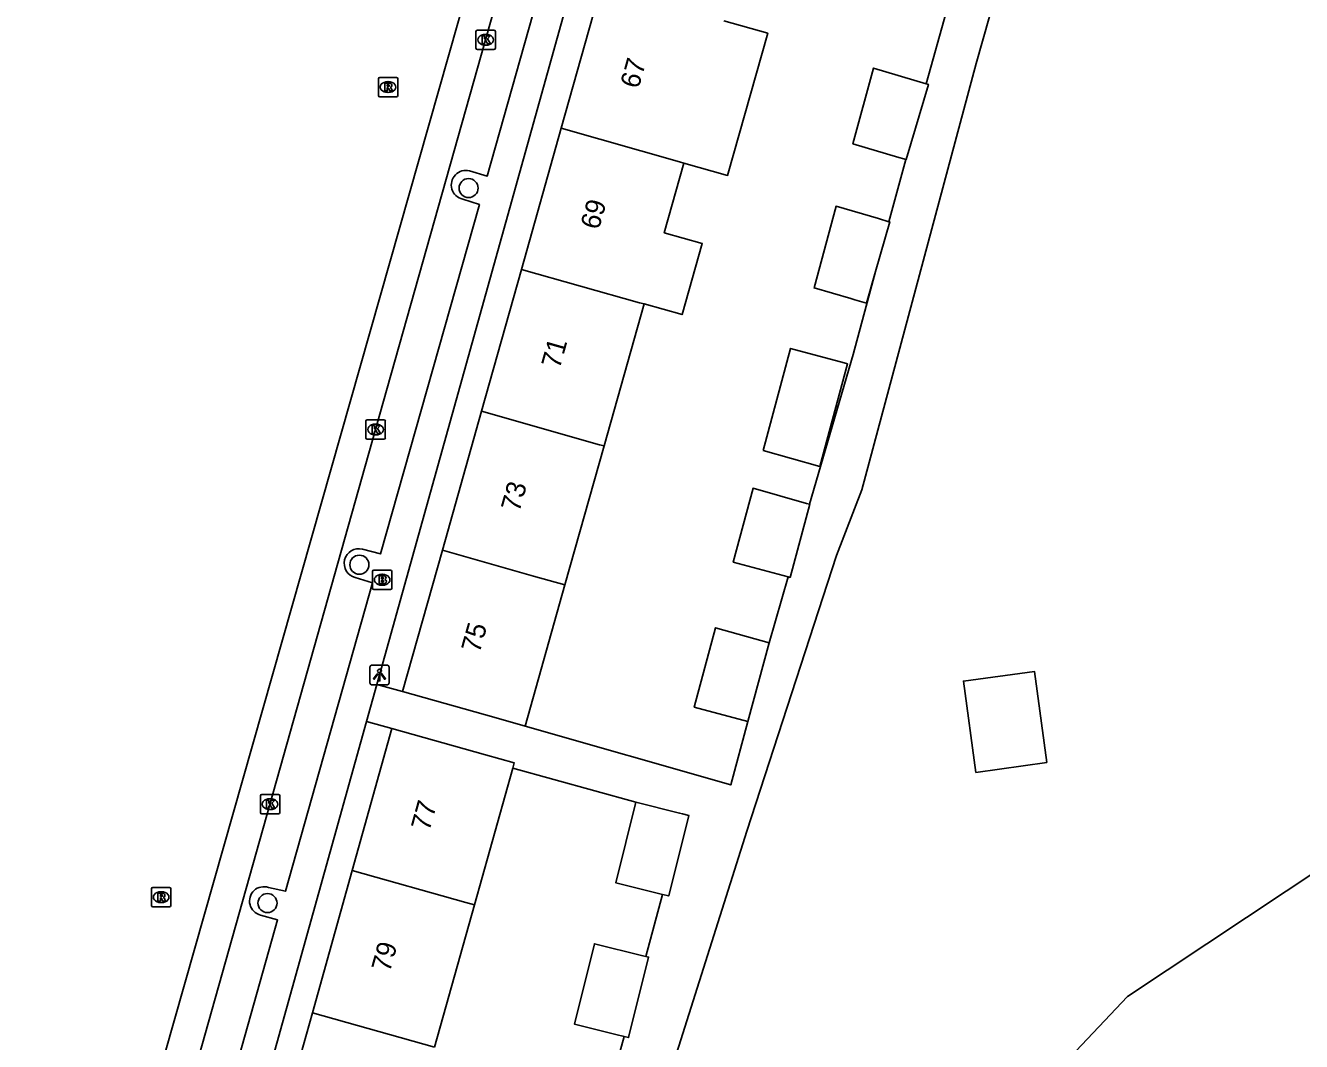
# Model space of a CAD drawing. Extents: x 163150 to 163546, y 380933 to 381635.
# Drawn here: x 163161.3 to 163226.9, y 381288.4 to 381340.6 of the extents above; entities that cross this region are included whole.
import ezdxf

# ---------------------------------------------------------------- set-up
doc = ezdxf.new("R2010")
doc.units = 0
for name, color, linetype in [('IMGEO_Boom', 7, 'Continuous'), ('IMGEO_Brandkraan', 7, 'Continuous'), ('IMGEO_Fietspad_gesloten', 7, 'Continuous'), ('IMGEO_Kolk', 7, 'Continuous'), ('IMGEO_Lichtpunt', 7, 'Continuous'), ('IMGEO_Pand', 7, 'Continuous'), ('IMGEO_Pand_nummerreeks', 7, 'Continuous'), ('IMGEO_Rijbaan_lokaal_gesloten', 7, 'Continuous'), ('IMGEO_Rioolput', 7, 'Continuous'), ('IMGEO_Voetpad_open', 7, 'Continuous')]:
    doc.layers.add(name, color=color, linetype=linetype)

msp = doc.modelspace()

# ---------------------------------------------------------------- linework, layer by layer
at = {"layer": 'IMGEO_Boom'}
for centre in [(163184.057, 381332.261), (163178.441, 381312.89), (163173.717, 381295.486)]:
    msp.add_circle(centre, 0.489, dxfattribs=at)
at = {"layer": 'IMGEO_Brandkraan'}
for p, q in [((163179.113, 381311.689), (163179.113, 381312.541)), ((163179.188, 381312.615), (163180.04, 381312.615)), ((163179.601, 381312.395), (163179.626, 381312.395)), ((163180.114, 381312.541), (163180.114, 381311.689)), ((163180.04, 381311.615), (163179.188, 381311.615)), ((163179.624, 381311.835), (163179.599, 381311.835))]:
    msp.add_line(p, q, dxfattribs=at)
for points in [[(163179.113, 381311.689), (163179.113, 381312.541)], [(163179.188, 381312.615), (163180.04, 381312.615)], [(163179.461, 381312.315), (163179.461, 381311.915), (163179.674, 381311.915)], [(163179.692, 381312.315), (163179.461, 381312.315)], [(163179.64, 381312.234), (163179.586, 381312.234), (163179.586, 381312.158)], [(163179.586, 381312.158), (163179.639, 381312.158)], [(163179.648, 381312.082), (163179.586, 381312.082), (163179.586, 381312.001)], [(163180.114, 381312.541), (163180.114, 381311.689)], [(163180.04, 381311.615), (163179.188, 381311.615)], [(163179.586, 381312.001), (163179.648, 381312.001)]]:
    msp.add_lwpolyline(points, dxfattribs=at)
for centre, radius, start, end in [((163179.19, 381312.539), 0.0765, 91.55205, 178.44795), ((163179.19, 381312.539), 0.0765, 91.55205, 178.44795), ((163179.641, 381312.196), 0.0379, 267.82845, 90.93552), ((163179.649, 381312.041), 0.0404, 269.87594, 90.50774), ((163179.696, 381312.17), 0.145, 59.4692, 91.53667), ((163179.721, 381312.217), 0.0922, 285.51372, 58.15012), ((163179.726, 381312.025), 0.105, 301.31148, 78.98903), ((163180.038, 381312.539), 0.0765, 1.55205, 88.44795), ((163180.038, 381312.539), 0.0765, 1.55205, 88.44795), ((163179.19, 381311.691), 0.0765, 181.55205, 268.44795), ((163179.19, 381311.691), 0.0765, 181.55205, 268.44795), ((163179.68, 381312.166), 0.251, 268.66757, 293.53466), ((163180.038, 381311.691), 0.0765, 271.55205, 358.44795), ((163180.038, 381311.691), 0.0765, 271.55205, 358.44795)]:
    msp.add_arc(centre, radius, start, end, dxfattribs=at)
for centre, major_axis, ratio, start_param, end_param in [((163179.6, 381312.115), (-0.387, 0.002), 0.722429, 4.712389, 7.853982), ((163179.625, 381312.115), (-0.39, 0.002), 0.717154, 1.570796, 4.712389)]:
    msp.add_ellipse(centre, major_axis=major_axis, ratio=ratio, start_param=start_param, end_param=end_param, dxfattribs=at)
at = {"layer": 'IMGEO_Fietspad_gesloten'}
msp.add_lwpolyline([(163161.275, 381254.943), (163161.793, 381257.499), (163168.406, 381281.262), (163179.271, 381319.843), (163184.929, 381339.887), (163190.292, 381358.866), (163196.902, 381382.418), (163200.87, 381396.808), (163201.039, 381397.48), (163201.153, 381398.031), (163202.014, 381403.062), (163202.729, 381407.262)], dxfattribs=at)
at = {"layer": 'IMGEO_Kolk'}
for p, q in [((163184.433, 381339.461), (163184.433, 381340.313)), ((163184.508, 381340.387), (163185.36, 381340.387)), ((163185.434, 381340.313), (163185.434, 381339.461)), ((163184.944, 381339.607), (163184.919, 381339.607)), ((163184.921, 381340.167), (163184.946, 381340.167)), ((163185.36, 381339.387), (163184.508, 381339.387)), ((163178.775, 381319.417), (163178.775, 381320.269)), ((163178.85, 381320.343), (163179.702, 381320.343)), ((163179.263, 381320.123), (163179.288, 381320.123)), ((163179.776, 381320.269), (163179.776, 381319.417)), ((163179.702, 381319.343), (163178.85, 381319.343)), ((163179.286, 381319.563), (163179.261, 381319.563)), ((163173.349, 381300.149), (163173.349, 381301.001)), ((163173.424, 381301.075), (163174.276, 381301.075)), ((163174.35, 381301.001), (163174.35, 381300.149)), ((163173.86, 381300.295), (163173.835, 381300.295)), ((163173.837, 381300.855), (163173.862, 381300.855)), ((163174.276, 381300.075), (163173.424, 381300.075))]:
    msp.add_line(p, q, dxfattribs=at)
for points in [[(163184.433, 381339.461), (163184.433, 381340.313)], [(163184.508, 381340.387), (163185.36, 381340.387)], [(163185.434, 381340.313), (163185.434, 381339.461)], [(163184.754, 381340.087), (163184.877, 381340.087), (163184.877, 381339.936), (163185.007, 381340.087), (163185.171, 381340.087), (163185.025, 381339.936), (163185.178, 381339.687), (163185.026, 381339.687), (163184.941, 381339.851), (163184.877, 381339.784), (163184.877, 381339.687), (163184.754, 381339.687), (163184.754, 381340.087)], [(163185.36, 381339.387), (163184.508, 381339.387)], [(163178.775, 381319.417), (163178.775, 381320.269)], [(163178.85, 381320.343), (163179.702, 381320.343)], [(163179.096, 381320.043), (163179.219, 381320.043), (163179.219, 381319.892), (163179.349, 381320.043), (163179.513, 381320.043), (163179.367, 381319.892), (163179.52, 381319.643), (163179.368, 381319.643), (163179.283, 381319.807), (163179.219, 381319.74), (163179.219, 381319.643), (163179.096, 381319.643), (163179.096, 381320.043)], [(163179.776, 381320.269), (163179.776, 381319.417)], [(163179.702, 381319.343), (163178.85, 381319.343)], [(163173.349, 381300.149), (163173.349, 381301.001)], [(163173.424, 381301.075), (163174.276, 381301.075)], [(163174.35, 381301.001), (163174.35, 381300.149)], [(163173.67, 381300.775), (163173.793, 381300.775), (163173.793, 381300.624), (163173.923, 381300.775), (163174.087, 381300.775), (163173.941, 381300.624), (163174.094, 381300.375), (163173.942, 381300.375), (163173.857, 381300.539), (163173.793, 381300.472), (163173.793, 381300.375), (163173.67, 381300.375), (163173.67, 381300.775)], [(163174.276, 381300.075), (163173.424, 381300.075)]]:
    msp.add_lwpolyline(points, dxfattribs=at)
for centre, start, end in [((163184.51, 381340.311), 91.55205, 178.44795), ((163184.51, 381340.311), 91.55205, 178.44795), ((163185.358, 381340.311), 1.55205, 88.44795), ((163185.358, 381340.311), 1.55205, 88.44795), ((163184.51, 381339.463), 181.55205, 268.44795), ((163184.51, 381339.463), 181.55205, 268.44795), ((163185.358, 381339.463), 271.55205, 358.44795), ((163185.358, 381339.463), 271.55205, 358.44795), ((163178.852, 381320.267), 91.55205, 178.44795), ((163178.852, 381320.267), 91.55205, 178.44795), ((163179.7, 381320.267), 1.55205, 88.44795), ((163179.7, 381320.267), 1.55205, 88.44795), ((163178.852, 381319.419), 181.55205, 268.44795), ((163178.852, 381319.419), 181.55205, 268.44795), ((163179.7, 381319.419), 271.55205, 358.44795), ((163179.7, 381319.419), 271.55205, 358.44795), ((163173.426, 381300.999), 91.55205, 178.44795), ((163173.426, 381300.999), 91.55205, 178.44795), ((163174.274, 381300.999), 1.55205, 88.44795), ((163174.274, 381300.999), 1.55205, 88.44795), ((163173.426, 381300.151), 181.55205, 268.44795), ((163173.426, 381300.151), 181.55205, 268.44795), ((163174.274, 381300.151), 271.55205, 358.44795), ((163174.274, 381300.151), 271.55205, 358.44795)]:
    msp.add_arc(centre, 0.0765, start, end, dxfattribs=at)
for centre, major_axis, ratio, start_param, end_param in [((163184.92, 381339.887), (-0.387, 0.002), 0.722429, 4.712389, 7.853982), ((163184.945, 381339.887), (-0.39, 0.002), 0.717154, 1.570796, 4.712389), ((163179.262, 381319.843), (-0.387, 0.002), 0.722429, 4.712389, 7.853982), ((163179.287, 381319.843), (-0.39, 0.002), 0.717154, 1.570796, 4.712389), ((163173.836, 381300.575), (-0.387, 0.002), 0.722429, 4.712389, 7.853982), ((163173.861, 381300.575), (-0.39, 0.002), 0.717154, 1.570796, 4.712389)]:
    msp.add_ellipse(centre, major_axis=major_axis, ratio=ratio, start_param=start_param, end_param=end_param, dxfattribs=at)
at = {"layer": 'IMGEO_Lichtpunt'}
for p, q in [((163178.978, 381307.62), (163178.978, 381306.813)), ((163178.978, 381307.62), (163178.978, 381306.813)), ((163179.88, 381307.715), (163179.072, 381307.715)), ((163179.88, 381307.715), (163179.072, 381307.715)), ((163179.974, 381306.813), (163179.974, 381307.62)), ((163179.974, 381306.813), (163179.974, 381307.62)), ((163179.072, 381306.719), (163179.88, 381306.719)), ((163179.072, 381306.719), (163179.88, 381306.719))]:
    msp.add_line(p, q, dxfattribs=at)
for points in [[(163179.352, 381307.284), (163179.391, 381307.256), (163179.203, 381306.994), (163179.165, 381307.021), (163179.352, 381307.284)], [(163179.454, 381307.236), (163179.501, 381307.236), (163179.501, 381306.914), (163179.454, 381306.914), (163179.454, 381307.236)], [(163179.564, 381307.256), (163179.602, 381307.283), (163179.789, 381307.021), (163179.75, 381306.993), (163179.564, 381307.256)]]:
    msp.add_lwpolyline(points, dxfattribs=at)
msp.add_circle((163179.477, 381307.418), 0.0994, dxfattribs=at)
for centre, start, end in [((163179.072, 381307.62), 90, 180), ((163179.072, 381307.62), 90, 180), ((163179.88, 381307.62), 0, 90), ((163179.88, 381307.62), 0, 90), ((163179.072, 381306.813), 180, 270), ((163179.072, 381306.813), 180, 270), ((163179.88, 381306.813), 270, 0), ((163179.88, 381306.813), 270, 360)]:
    msp.add_arc(centre, 0.0946, start, end, dxfattribs=at)
at = {"layer": 'IMGEO_Pand'}
for points in [[(163190.882, 381342.639), (163188.825, 381335.337)], [(163195.127, 381333.55), (163197.374, 381332.915), (163199.439, 381340.22), (163197.185, 381340.857)], [(163206.533, 381333.732), (163206.432, 381333.762), (163206.181, 381333.837), (163203.817, 381334.538), (163204.869, 381338.436), (163207.581, 381337.631)], [(163207.581, 381337.631), (163207.703, 381337.595), (163206.554, 381333.726), (163206.533, 381333.732)], [(163188.825, 381335.337), (163186.781, 381328.079)], [(163195.127, 381333.55), (163194.895, 381333.616), (163188.825, 381335.337)], [(163193.085, 381326.302), (163195.035, 381325.75), (163196.07, 381329.405), (163194.115, 381329.959), (163195.127, 381333.55)], [(163204.982, 381327.966), (163204.513, 381326.347), (163203.921, 381326.519), (163203.711, 381326.58), (163201.818, 381327.129), (163202.95, 381331.323), (163205.13, 381330.691), (163205.673, 381330.533)], [(163205.673, 381330.533), (163205.722, 381330.519), (163204.982, 381327.966)], [(163186.781, 381328.079), (163184.724, 381320.778)], [(163186.781, 381328.079), (163192.842, 381326.362), (163193.085, 381326.302)], [(163191.028, 381318.999), (163193.085, 381326.302)], [(163199.206, 381318.759), (163202.119, 381317.934), (163203.541, 381323.228), (163203.376, 381323.272), (163200.617, 381324.012), (163199.206, 381318.759)], [(163184.724, 381320.778), (163182.71, 381313.629)], [(163191.028, 381318.999), (163190.78, 381319.062), (163184.724, 381320.778)], [(163189.013, 381311.846), (163191.028, 381318.999)], [(163200.497, 381312.262), (163197.665, 381313.023), (163198.686, 381316.821), (163201.434, 381316.043), (163201.588, 381316)], [(163201.588, 381316), (163201.598, 381315.997), (163200.588, 381312.237), (163200.497, 381312.262)], [(163182.71, 381313.629), (163180.663, 381306.36)], [(163189.013, 381311.846), (163187.391, 381312.302), (163182.71, 381313.629)], [(163186.97, 381304.591), (163189.013, 381311.846)], [(163187.968, 381233.07), (163193.271, 381250), (163197.467, 381263.396), (163206.151, 381278.206), (163217.937, 381290.687), (163232.209, 381300.168), (163248.202, 381306.183), (163251.969, 381306.664), (163251.737, 381308.49), (163248.676, 381308.083), (163248.28, 381310.782), (163251.461, 381311.208), (163254.337, 381311.635), (163256.45, 381311.907)], [(163198.421, 381304.829), (163195.663, 381305.57), (163196.758, 381309.646), (163199.506, 381308.868)], [(163199.506, 381308.868), (163198.421, 381304.829)], [(163213.795, 381302.708), (163210.142, 381302.21), (163209.502, 381306.907), (163213.155, 381307.404), (163213.795, 381302.708)], [(163180.663, 381306.36), (163185.478, 381305.01), (163186.97, 381304.591)], [(163178.075, 381297.165), (163180.119, 381304.459)], [(163186.332, 381302.428), (163186.406, 381302.694), (163184.933, 381303.108), (163180.119, 381304.459)], [(163186.332, 381302.428), (163184.36, 381295.392)], [(163194.036, 381295.935), (163191.624, 381296.533), (163192.652, 381300.67)], [(163194.036, 381295.935), (163194.353, 381295.856), (163195.379, 381299.992), (163195.063, 381300.071), (163194.903, 381300.111), (163192.652, 381300.67)], [(163178.075, 381297.165), (163176.023, 381289.839)], [(163184.36, 381295.392), (163183.923, 381295.514), (163178.075, 381297.165)], [(163184.36, 381295.392), (163182.308, 381288.068)], [(163192.051, 381288.626), (163191.992, 381288.641), (163191.694, 381288.715), (163189.498, 381289.26), (163190.526, 381293.396), (163193.019, 381292.777), (163193.168, 381292.74)], [(163193.168, 381292.74), (163193.31, 381292.705), (163192.282, 381288.569), (163192.051, 381288.626)], [(163176.023, 381289.839), (163174.025, 381282.711)], [(163182.308, 381288.068), (163176.023, 381289.839)]]:
    msp.add_lwpolyline(points, dxfattribs=at)
at = {"layer": 'IMGEO_Rijbaan_lokaal_gesloten'}
msp.add_lwpolyline([(163166.425, 381280.691), (163188.546, 381358.485), (163194.244, 381378.759), (163197.853, 381391.449), (163199.503, 381397.64), (163199.813, 381399.806), (163200.997, 381406.978), (163202.361, 381414.066), (163203.421, 381419.565), (163203.421, 381421.474), (163203.421, 381430.45), (163203.421, 381436.022), (163203.704, 381437.827), (163206.489, 381449.486), (163214.12, 381481.676), (163216.801, 381492.716), (163218.451, 381497.565), (163223.711, 381513.764), (163241.568, 381568.239), (163248.986, 381592.289), (163253.519, 381605.619), (163255.545, 381608.986), (163259.826, 381616.311)], dxfattribs=at)
at = {"layer": 'IMGEO_Rioolput'}
for p, q in [((163179.417, 381337.03), (163179.417, 381337.882)), ((163179.492, 381337.956), (163180.344, 381337.956)), ((163179.905, 381337.736), (163179.93, 381337.736)), ((163180.418, 381337.882), (163180.418, 381337.03)), ((163179.928, 381337.176), (163179.903, 381337.176)), ((163180.344, 381336.956), (163179.492, 381336.956)), ((163167.825, 381296.292), (163168.677, 381296.292)), ((163167.75, 381295.366), (163167.75, 381296.218)), ((163168.238, 381296.072), (163168.263, 381296.072)), ((163168.751, 381296.218), (163168.751, 381295.366)), ((163168.677, 381295.292), (163167.825, 381295.292)), ((163168.261, 381295.512), (163168.236, 381295.512))]:
    msp.add_line(p, q, dxfattribs=at)
for points in [[(163179.417, 381337.03), (163179.417, 381337.882)], [(163179.492, 381337.956), (163180.344, 381337.956)], [(163180.006, 381337.654), (163179.754, 381337.656), (163179.754, 381337.256)], [(163180.418, 381337.882), (163180.418, 381337.03)], [(163179.754, 381337.256), (163179.878, 381337.256), (163179.878, 381337.418), (163179.889, 381337.418)], [(163179.932, 381337.575), (163179.878, 381337.575), (163179.878, 381337.494)], [(163179.878, 381337.494), (163179.93, 381337.494)], [(163179.936, 381337.389), (163180.007, 381337.256), (163180.147, 381337.256), (163180.082, 381337.382)], [(163180.344, 381336.956), (163179.492, 381336.956)], [(163167.825, 381296.292), (163168.677, 381296.292)], [(163167.75, 381295.366), (163167.75, 381296.218)], [(163168.339, 381295.99), (163168.087, 381295.992), (163168.087, 381295.592)], [(163168.087, 381295.592), (163168.211, 381295.592), (163168.211, 381295.754), (163168.222, 381295.754)], [(163168.265, 381295.911), (163168.211, 381295.911), (163168.211, 381295.83)], [(163168.211, 381295.83), (163168.263, 381295.83)], [(163168.269, 381295.725), (163168.34, 381295.592), (163168.48, 381295.592), (163168.415, 381295.718)], [(163168.751, 381296.218), (163168.751, 381295.366)], [(163168.677, 381295.292), (163167.825, 381295.292)]]:
    msp.add_lwpolyline(points, dxfattribs=at)
for centre, radius, start, end in [((163179.494, 381337.88), 0.0765, 91.55205, 178.44795), ((163179.494, 381337.88), 0.0765, 91.55205, 178.44795), ((163180.005, 381337.544), 0.109, 350.36119, 89.41601), ((163180.342, 381337.88), 0.0765, 1.55205, 88.44795), ((163180.342, 381337.88), 0.0765, 1.55205, 88.44795), ((163179.494, 381337.032), 0.0765, 181.55205, 268.44795), ((163179.494, 381337.032), 0.0765, 181.55205, 268.44795), ((163179.888, 381337.365), 0.0533, 26.02933, 88.69889), ((163179.914, 381337.683), 0.19, 274.7715, 282.96867), ((163179.938, 381337.479), 0.0964, 77.00612, 93.18647), ((163179.952, 381337.536), 0.0378, 276.66336, 79.67722), ((163180.003, 381337.544), 0.112, 277.58423, 350.98172), ((163179.987, 381337.329), 0.108, 29.51342, 73.79051), ((163180.342, 381337.032), 0.0765, 271.55205, 358.44795), ((163180.342, 381337.032), 0.0765, 271.55205, 358.44795), ((163167.827, 381296.216), 0.0765, 91.55205, 178.44795), ((163167.827, 381296.216), 0.0765, 91.55205, 178.44795), ((163168.675, 381296.216), 0.0765, 1.55205, 88.44795), ((163168.675, 381296.216), 0.0765, 1.55205, 88.44795), ((163168.221, 381295.701), 0.0533, 26.02933, 88.69889), ((163168.247, 381296.019), 0.19, 274.7715, 282.96867), ((163168.271, 381295.815), 0.0964, 77.00612, 93.18647), ((163168.285, 381295.872), 0.0378, 276.66336, 79.67722), ((163168.338, 381295.88), 0.109, 350.36119, 89.41601), ((163168.336, 381295.88), 0.112, 277.58423, 350.98172), ((163168.32, 381295.665), 0.108, 29.51342, 73.79051), ((163167.827, 381295.368), 0.0765, 181.55205, 268.44795), ((163167.827, 381295.368), 0.0765, 181.55205, 268.44795), ((163168.675, 381295.368), 0.0765, 271.55205, 358.44795), ((163168.675, 381295.368), 0.0765, 271.55205, 358.44795)]:
    msp.add_arc(centre, radius, start, end, dxfattribs=at)
for centre, major_axis, ratio, start_param, end_param in [((163179.904, 381337.456), (-0.387, 0.002), 0.722429, 4.712389, 7.853982), ((163179.929, 381337.456), (-0.39, 0.002), 0.717154, 1.570796, 4.712389), ((163168.237, 381295.792), (-0.387, 0.002), 0.722429, 4.712389, 7.853982), ((163168.262, 381295.792), (-0.39, 0.002), 0.717154, 1.570796, 4.712389)]:
    msp.add_ellipse(centre, major_axis=major_axis, ratio=ratio, start_param=start_param, end_param=end_param, dxfattribs=at)
at = {"layer": 'IMGEO_Voetpad_open'}
for points in [[(163237.977, 381426.449), (163234.394, 381426.061), (163227.903, 381401.347), (163219.779, 381373.21), (163217.039, 381362.987), (163210.152, 381338.67), (163208.061, 381330.864), (163204.278, 381316.746), (163202.976, 381313.355), (163198.372, 381299.184), (163184.779, 381256.196), (163183.349, 381256.587), (163188.12, 381274.155)], [(163179.345, 381306.73), (163193.522, 381357.567)], [(163188.83, 381349.795), (163189.717, 381349.519), (163185.017, 381332.879), (163184.107, 381333.145)], [(163208.63, 381341.355), (163207.581, 381337.631)], [(163206.533, 381333.732), (163205.673, 381330.533)], [(163183.756, 381331.691), (163184.613, 381331.42), (163179.525, 381313.448), (163178.599, 381313.689)], [(163204.982, 381327.966), (163203.834, 381323.696), (163201.588, 381316)], [(163178.23, 381312.224), (163179.116, 381311.955), (163174.648, 381296.092), (163173.77, 381296.291)], [(163200.497, 381312.262), (163199.506, 381308.868)], [(163178.814, 381304.825), (163179.345, 381306.73)], [(163179.345, 381306.73), (163180.663, 381306.36)], [(163165.917, 381253.773), (163164.683, 381254.152), (163178.814, 381304.825)], [(163180.119, 381304.459), (163178.814, 381304.825)], [(163198.421, 381304.829), (163197.534, 381301.564), (163186.97, 381304.591)], [(163192.652, 381300.67), (163186.332, 381302.428)], [(163193.168, 381292.74), (163194.036, 381295.935)], [(163173.36, 381294.872), (163174.233, 381294.63), (163169.487, 381277.734), (163168.599, 381277.989)], [(163191.174, 381285.399), (163192.051, 381288.626)]]:
    msp.add_lwpolyline(points, dxfattribs=at)
for centre, radius, start, end in [((163183.915, 381332.422), 0.748, 75.13345, 257.72312), ((163178.416, 381312.956), 0.755, 76.00986, 255.71529), ((163173.534, 381295.59), 0.739, 71.38773, 256.38047)]:
    msp.add_arc(centre, radius, start, end, dxfattribs=at)

# ---------------------------------------------------------------- texts
at = {"layer": 'IMGEO_Pand_nummerreeks'}
for s, rotation, p in [('67', 74.2686, (163192.795, 381337.332)), ('69', 74.26679, (163190.75, 381330.075)), ('71', 74.2686, (163188.738, 381322.927)), ('73', 74.2686, (163186.663, 381315.561)), ('75', 74.2686, (163184.618, 381308.304)), ('77', 74.347, (163182.038, 381299.149)), ('79', 74.34734, (163180.003, 381291.889))]:
    msp.add_text(s, height=1, rotation=rotation, dxfattribs=at).set_placement(p)

doc.saveas('drawing.dxf')
